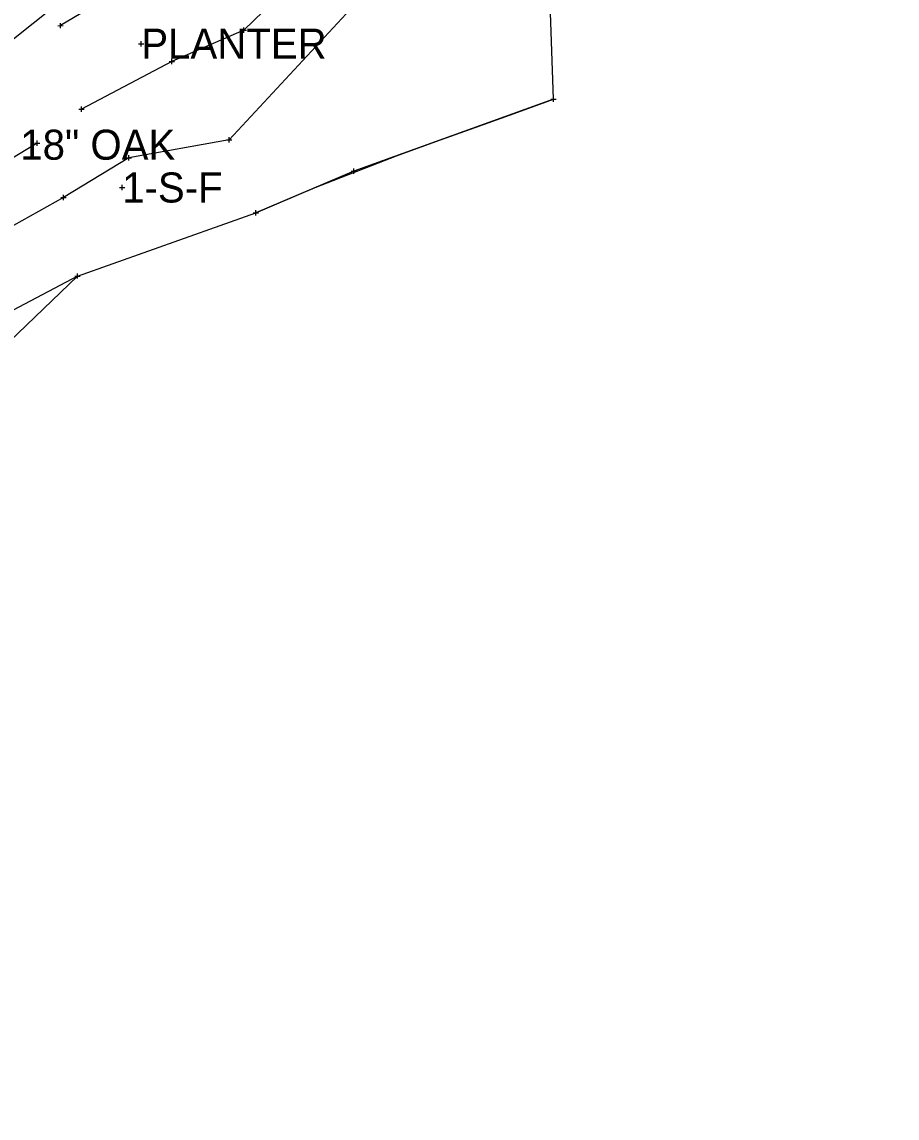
# Model space of a CAD drawing. Extents: x -1 to 1157254, y -1 to 2021979.
# Drawn here: x 1150221.6 to 1150431.2, y 2019250.9 to 2019513.5 of the extents above; entities that cross this region are included whole.
import ezdxf

# ---------------------------------------------------------------- set-up
doc = ezdxf.new("R2010")
doc.units = 0
for name, color, linetype in [('S_BUILDING_ANNOT', 7, 'Continuous'), ('S_CTL_TABLE', 7, 'Continuous'), ('S_EDGE_BITUMINOUS_ANNOT', 7, 'Continuous'), ('S_FENCE', 7, 'Continuous'), ('S_GAS_PUMP_ISLAND_ANNOT', 7, 'Continuous'), ('S_GATE', 7, 'Continuous'), ('S_GATE_ANNOT', 7, 'Continuous')]:
    doc.layers.add(name, color=color, linetype=linetype)

msp = doc.modelspace()

# ---------------------------------------------------------------- linework, layer by layer
at = {"layer": 'S_BUILDING_ANNOT'}
for p, q in [((1150249.56, 2019508.27), (1150250.83, 2019508.28)), ((1150250.19, 2019507.64), (1150250.19, 2019508.91)), ((1150250.19, 2019508.28), (1150250.19, 2019508.28)), ((1150244.97, 2019473.83), (1150246.24, 2019473.83)), ((1150245.61, 2019473.2), (1150245.61, 2019474.47)), ((1150245.61, 2019473.83), (1150245.61, 2019473.83))]:
    msp.add_line(p, q, dxfattribs=at)
at = {"layer": 'S_CTL_TABLE'}
for p, q in [((1150230.23, 2019512.59), (1150231.51, 2019512.6)), ((1150230.87, 2019511.96), (1150230.87, 2019513.23)), ((1150230.87, 2019512.6), (1150230.87, 2019512.6)), ((1150274.14, 2019511.51), (1150275.42, 2019511.51)), ((1150274.78, 2019510.87), (1150274.78, 2019512.15)), ((1150274.78, 2019511.51), (1150274.78, 2019511.51)), ((1150257.47, 2019503.37), (1150257.47, 2019504.64)), ((1150256.84, 2019504.01), (1150258.11, 2019504.01)), ((1150257.47, 2019504.01), (1150257.47, 2019504.01)), ((1150348.32, 2019494.95), (1150349.59, 2019494.95)), ((1150348.96, 2019494.32), (1150348.96, 2019495.59)), ((1150348.96, 2019494.95), (1150348.96, 2019494.95)), ((1150235.26, 2019492.57), (1150236.53, 2019492.57)), ((1150235.9, 2019491.93), (1150235.9, 2019493.2)), ((1150235.9, 2019492.57), (1150235.9, 2019492.57)), ((1150224.58, 2019484.44), (1150225.86, 2019484.44)), ((1150225.22, 2019483.8), (1150225.22, 2019485.08)), ((1150225.22, 2019484.44), (1150225.22, 2019484.44)), ((1150270.61, 2019485.26), (1150271.89, 2019485.27)), ((1150271.25, 2019484.63), (1150271.25, 2019485.9)), ((1150271.25, 2019485.26), (1150271.25, 2019485.26)), ((1150246.58, 2019480.93), (1150247.85, 2019480.94)), ((1150247.21, 2019480.3), (1150247.21, 2019481.57)), ((1150247.21, 2019480.94), (1150247.21, 2019480.94)), ((1150301.09, 2019477.11), (1150301.08, 2019478.38)), ((1150300.45, 2019477.75), (1150301.72, 2019477.75)), ((1150301.09, 2019477.75), (1150301.09, 2019477.75)), ((1150230.89, 2019471.45), (1150232.17, 2019471.46)), ((1150231.53, 2019470.82), (1150231.53, 2019472.09)), ((1150231.53, 2019471.46), (1150231.53, 2019471.46)), ((1150277.61, 2019467.13), (1150277.6, 2019468.4)), ((1150276.97, 2019467.76), (1150278.24, 2019467.76)), ((1150277.61, 2019467.76), (1150277.61, 2019467.76)), ((1150234.26, 2019452.62), (1150235.53, 2019452.62)), ((1150234.9, 2019451.99), (1150234.9, 2019453.26)), ((1150234.9, 2019452.62), (1150234.9, 2019452.62))]:
    msp.add_line(p, q, dxfattribs=at)
at = {"layer": 'S_EDGE_BITUMINOUS_ANNOT'}
for points in [[(1150346.72, 2019587.58), (1150319.73, 2019580.37), (1150276.31, 2019529.58), (1150250.87, 2019524.53), (1150230.87, 2019512.6)], [(1150349.05, 2019558.23), (1150312.56, 2019548.11), (1150274.78, 2019511.51), (1150257.47, 2019504.01), (1150235.9, 2019492.57)], [(1150347.67, 2019531.84), (1150310.7, 2019527.77), (1150271.25, 2019485.26), (1150247.21, 2019480.94), (1150231.53, 2019471.46), (1150209.53, 2019459.1)], [(1150348.96, 2019494.95), (1150301.09, 2019477.75), (1150277.61, 2019467.76)], [(1150225.22, 2019484.44), (1150204, 2019471.61)], [(1150234.9, 2019452.62), (1150216.64, 2019442.91)]]:
    msp.add_lwpolyline(points, dxfattribs=at)
at = {"layer": 'S_FENCE'}
msp.add_lwpolyline([(1150775.16, 2019913.88), (1150697.15, 2019862.05), (1150611.54, 2019805.47), (1150516.86, 2019735.37), (1150402.98, 2019659.79), (1150352.98, 2019622.15), (1150350.25, 2019606.72), (1150331.34, 2019598.55), (1150196.24, 2019490.87), (1150043.62, 2019380.11), (1149966.77, 2019324.72), (1149934.21, 2019308.48), (1149916.33, 2019289.12), (1149866.68, 2019250.91)], dxfattribs=at)
at = {"layer": 'S_GAS_PUMP_ISLAND_ANNOT'}
msp.add_lwpolyline([(1150218.58, 2019436.94), (1150234.9, 2019452.62), (1150277.61, 2019467.76), (1150282.68, 2019469.92), (1150291.88, 2019473.83), (1150311.32, 2019481.43), (1150320.73, 2019484.81), (1150330.14, 2019488.19), (1150339.55, 2019491.57), (1150348.96, 2019494.95), (1150347.67, 2019531.84)], dxfattribs=at)

# ---------------------------------------------------------------- texts
at = {"layer": 'S_GATE'}
for s, p in [('PLANTER', (1150250.19, 2019504.68)), ('1-S-F', (1150245.61, 2019470.23))]:
    msp.add_text(s, height=7.2, dxfattribs=at).set_placement(p)
at = {"layer": 'S_GATE_ANNOT'}
msp.add_text('18" OAK', height=7.2, dxfattribs=at).set_placement((1150221.2, 2019480.48))

doc.saveas('drawing.dxf')
